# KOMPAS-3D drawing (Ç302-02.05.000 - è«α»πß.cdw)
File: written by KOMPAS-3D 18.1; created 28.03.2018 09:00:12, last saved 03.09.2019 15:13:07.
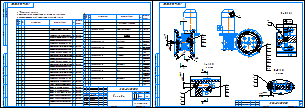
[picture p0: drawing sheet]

Sheets 1-2: A3, landscape

Document properties: Автор: Милов; Полное имя файла: \\192.168.87.28\Konstructor_doc\Мембранные насосы\Мембранный электропривод\А302-00.00.000 - ASTRA-302 (МЭ200)\Чертежи ПВХ\..\3Д ПВХ\А302-01.05.000 - Корпус.a3d; Масса: 33.4594; Форматы листов документа: 2xA3

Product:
- Part/product: (unnamed)
  - Component: Подшипник 80х40х18 6208-2RS1 SKF  | pos. 21  | Раздел спецификации: Стандартные изделия
  - Component: Шайба C.8.21 ГОСТ 11371-78  | pos. 20  | Раздел спецификации: Стандартные изделия; Примечание: Нерж.
  - Component: Шайба C.5.21 ГОСТ 11371-78  | pos. 19  | Раздел спецификации: Стандартные изделия; Примечание: Нерж.
  - Component: Шайба C 8 ГОСТ 6958-78  | pos. 18  | Раздел спецификации: Стандартные изделия; Примечание: Нерж.
  - Component: Шайба 8 ГОСТ 6402-70  | pos. 17  | Раздел спецификации: Стандартные изделия; Примечание: Нерж.
  - Component: Шайба 5 ГОСТ 6402-70  | pos. 16  | Раздел спецификации: Стандартные изделия; Примечание: Нерж.
  - Component: Кольцо A40.65Г ГОСТ 13942-86  | pos. 15  | Раздел спецификации: Стандартные изделия
  - Component: Гайка М8-6H ГОСТ 5915-70  | pos. 14  | Раздел спецификации: Стандартные изделия; Примечание: Нерж.
  - Component: Винт с цилиндрической головкой. / и шестигранным углублением под ключ / ГОСТ Р ИСО 4762-М8 x 45  | pos. 13  | Раздел спецификации: Стандартные изделия; Примечание: Нерж.
  - Component: Винт с цилиндрической головкой. / и шестигранным углублением под ключ / ГОСТ Р ИСО 4762-М8 x 35  | pos. 12  | Раздел спецификации: Стандартные изделия; Примечание: Нерж.
  - Component: Винт с цилиндрической головкой. / и шестигранным углублением под ключ / ГОСТ Р ИСО 4762-М5 x 16  | pos. 11  | Раздел спецификации: Стандартные изделия; Примечание: Нерж.
  - Component: Винт с цилиндрической головкой. / и шестигранным углублением под ключ / ГОСТ Р ИСО 4762-М5 x 12  | pos. 10  | Раздел спецификации: Стандартные изделия; Примечание: Нерж.
  - Component: Винт с потайной головкой / и шестигранным углублением под ключ / ГОСТ Р ИСО 10642-М4 x 20  | pos. 9  | Раздел спецификации: Стандартные изделия; Примечание: Нерж.
  - Component: Болт М8-6gx30 ГОСТ 7805-70  | pos. 8  | Раздел спецификации: Стандартные изделия; Примечание: Нерж.
  - Component: Фиксатор  | designation А302-01.05.015  | pos. 7  | Раздел спецификации: Детали; Форматы листов документа: А4; Примечание: Сталь 40  / ГОСТ 1050-2013 / @2~20
  - Component: Упор  | designation А302-01.05.014  | pos. 6  | Раздел спецификации: Детали; Форматы листов документа: А3; Примечание: Сталь 20  / ГОСТ 1050-2013 / Лист 30
  - Component: Фиксатор  | designation А302-01.05.012  | pos. 5  | Раздел спецификации: Детали; Форматы листов документа: А3; Примечание: Д16Т ГОСТ 4784-97 / Лист 20
  - Component: Ловитель  | designation А302-01.05.011  | pos. 4  | Раздел спецификации: Детали; Форматы листов документа: А4; Примечание: Сталь 40  / ГОСТ 1050-2013 / @2~10
  - Component: Ловитель  | designation А302-01.05.002  | pos. 3  | Раздел спецификации: Детали; Форматы листов документа: А3; Примечание: Фторопласт-4 / ГОСТ 10007-80 Е / @2~50
  - Component: Основание  | designation А302-01.05.001  | pos. 2  | Раздел спецификации: Детали; Форматы листов документа: А3; Примечание: Стержень ПВХ / @2~300
  - Component: Мотор-редуктор  | designation А302-02.20.000  | pos. 1  | Раздел спецификации: Сборочные единицы; Форматы листов документа: 2xA3; Примечание: *)2xA3

Title block, sheet 1: Наименование: Корпус; designation: А302-02.05.000; Масса: 33,46; scale: 1:4; sheet number: 1; Количество листов документа: 2; organisation: АО «Астерион»; Форматы листов документа: A3; stored path: Z:\Мембранные насосы\Мембранный электропривод\А302-00.00.000 - ASTRA-302 (МЭ200)\Чертежи\А302-00.05.000 - Корпус.cdw; Разработал: Лифлянд; Проверил: Борисенко; Т. контр.: Лучихин; Утвердил: Григорьева
Title block, sheet 2: sheet number: 2; stored path: Z:\Мембранные насосы\Мембранный электропривод\А302-00.00.000 - ASTRA-302 (МЭ200)\3Д ПВХ\А302-01.05.000 - Корпус.cdw

Views: Разрез А-А, Разрез Б-Б, Разрез В-В
Referenced files in D:\Мембранные насосы\Мембранный электропривод\А302-00.00.000 - ASTRA-302 (МЭ200)\3Д ПВХ\Отработка\: А302-01.20.000 - Мотор-редуктор.a3d, А302-01.05.002 - Ловитель.m3d, Упор-1.m3d, Фиксатор.m3d
Referenced files in Z:\Мембранные насосы\Мембранный электропривод\А302-00.00.000 - ASTRA-302 (МЭ200)\3Д ПВХ\: А302-01.20.000 - Мотор-редуктор.cdw
Referenced files in D:\Мембранные насосы\Мембранный электропривод\А302-00.00.000 - ASTRA-302 (МЭ200)\3Д ПВХ\: А302-01.05.002 - Ловитель.cdw, А302-01.05.001 - Основание.m3d, А302-01.05.001 - Основание.cdw, А302-01.05.012 - Фиксатор.m3d, А302-01.05.012 - Фиксатор.cdw, А302-01.05.014 - Упор.cdw, А302-01.05.011 - Ловитель.m3d, А302-01.05.011 - Ловитель.cdw, А302-01.05.015 - Фиксатор.m3d, А302-01.05.015 - Фиксатор.cdw, А302-01.20.001 - Основание.m3d, А302-01.35.000 - Фланец.a3d, А302-01.20.002 - Эксцентрик.m3d, А302-01.05.000 - Корпус.a3d
Referenced files in D:\1 ПКИ 3D\1 Крепеж стандартный\Подшипник\: Подшипник 80х40х18 6208-2RS1 SKF.m3d, Подшипник 52х25х15 62052RSH SKF.m3d
Referenced files in D:\1 ПКИ 3D\Двигатели\АИР\: Электродвигатель АИР 80А4 IM 3081 1,1кВт 1400 об..m3d
Referenced files in D:\1 ПКИ 3D\Редуктора NMRW\Редукторы\: Редуктор NMRW 063.m3d, Червячный мотор-редуктор NMRV063 АИР80.a3d
Referenced files in D:\Мембранные насосы\Мембранный электропривод\А302-00.00.000 - ASTRA-302 (МЭ200)\3Д\: А302-00.35.002 - Пластина.m3d, А302-00.35.001 - Труба 140х140х4.m3d, А302-00.20.004 - Вал.m3d, А302-00.20.003 - Ползун.m3d, А302-00.05.001 - Основание.m3d
Referenced files in C:\Program Files\ASCON\KOMPAS-3D v18\Libs\PartLib\DATA\VAULT\methods\kompas\3d\: PLib_Check_spring_rings_GOST_13942_911.m3d, PLib_Washer_1_712.m3d, PLib_Bolt_1_900.m3d, PLib_Washer_2_712.m3d, PLib_Nut_OST92_900.m3d, PLib_Screw_DIN_7984_1500.m3d, PLib_Key_prismatic_712.m3d, PLib_Screw_ISO_10642_1500.m3d
Referenced files in C:\Program Files\ASCON\KOMPAS-3D V16\Libs\PartLib\DATA\VAULT\Methods\kompas\3d\: PLib_Bolt_1_900.m3d
Referenced files in Z:\Мембранные насосы\Мембранный электропривод\А302-00.00.000 - ASTRA-302 (МЭ200)\3Д\: А302-00.20.002 - Эксцентрик.m3d
Referenced files in \\192.168.87.28\Konstructor_doc\Мембранные насосы\Мембранный электропривод\А302-00.00.000 - ASTRA-302 (МЭ200)\3Д ПВХ\Отработка\: А302-01.05.000 - Корпус.a3d, Фиксатор.m3d, Упор-1.m3d
Referenced files in C:\Program Files\ASCON\KOMPAS-3D V16\Libs\PartLib\DATA\vault\Methods\Kompas\3D\: PLib_Check_spring_rings_GOST_13942_911.m3d, PLib_Washer_2_712.m3d, PLib_Washer_1_712.m3d, PLib_Screw_DIN_7984_1500.m3d
Referenced files in \\192.168.87.28\Konstructor_doc\Мембранные насосы\Мембранный электропривод\А302-00.00.000 - ASTRA-302 (МЭ200)\3Д\: А302-00.20.004 - Вал.m3d, А302-00.35.001 - Труба 140х140х4.m3d, А302-00.35.002 - Пластина.m3d, А302-00.20.003 - Ползун.m3d
Referenced files in \\192.168.87.28\Konstructor_doc\1 ПКИ 3D\Двигатели\АИР\: Электродвигатель АИР 80А4 IM 3081 1,1кВт 1400 об..m3d
Referenced files in \\192.168.87.28\Konstructor_doc\Мембранные насосы\Мембранный электропривод\А302-00.00.000 - ASTRA-302 (МЭ200)\3Д ПВХ\: А302-01.20.002 - Эксцентрик.m3d, А302-01.05.001 - Основание.m3d, А302-01.05.011 - Ловитель.m3d, А302-01.05.012 - Фиксатор.m3d, А302-01.05.015 - Фиксатор.m3d
Referenced files in \\192.168.87.28\Konstructor_doc\1 ПКИ 3D\1 Крепеж стандартный\Подшипник\: Подшипник 80х40х18 6208-2RS1 SKF.m3d, Подшипник 52х25х15 62052RSH SKF.m3d
Referenced files in \\192.168.87.28\Konstructor_doc\1 ПКИ 3D\Редуктора NMRW\Редукторы\: Редуктор NMRW 063.m3d
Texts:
  Мотор-редуктор
  @100~)2xA3
  Ловитель
  Основание
  Шайба C.8.21 ГОСТ 11371-78
  Крепежное изделие ГОСТ
  Шайба
  ГОСТ
  нерж.
  Сталь 12Х18Н10Т ГОСТ 5632-72
  Шайба C 8 ГОСТ 6958-78
  Сталь 20 ГОСТ 1050-2013
  Шайба C 8.04.019 ГОСТ 6958-78
  Шайба 8 ГОСТ 6402-70
  Сталь 30Х13 ГОСТ 5632-72
  Шайба 8 30Х13 019 ГОСТ 6402-70
  Болт М8-6gx30 ГОСТ 7805-70
  Болт
  Болт М8-6gx30.58.019 ГОСТ 7805-70
  Гайка М8-6H ГОСТ 5915-70
  Гайка
  Гайка М8-6H.5.019 ГОСТ 5915-70
  Подшипник 80х40х18 6208-2RS1 SKF
  Подшипник
  SKF
  Фиксатор
  Упор
  Шайба C.5.21 ГОСТ 11371-78
  Шайба 5 ГОСТ 6402-70
  Винт с цилиндрической головкой
  и шестигранным углублением под ключ
  ГОСТ Р ИСО  4762-М5 x 16
  Винт с цилиндрической головкой и шестигранным углублением под ключ
  Р ИСО
  Сталь
  Шайба 5 30Х13 019 ГОСТ 6402-70
  Винт с цилиндрической головкой и шестигранным углублением под ключ ГОСТ Р ИСО  4762-М5 x 16-6.8-A9J
  ГОСТ Р ИСО  4762-М5 x 12
  Винт с цилиндрической головкой и шестигранным углублением под ключ ГОСТ Р ИСО  4762-М5 x 12-6.8-A9J
  Винт с потайной головкой
  ГОСТ Р ИСО  10642-М4 x 20
  Винт с потайной головкой и шестигранным углублением под ключ
  Винт с потайной головкой и шестигранным углублением под ключ ГОСТ Р ИСО  10642-М4 x 20-8.8-A3J
  ГОСТ Р ИСО  4762-М8 x 45
  Винт с цилиндрической головкой и шестигранным углублением под ключ ГОСТ Р ИСО  4762-М8 x 45-6.8-A9J
  ГОСТ Р ИСО  4762-М8 x 35
  Винт с цилиндрической головкой и шестигранным углублением под ключ ГОСТ Р ИСО  4762-М8 x 35-6.8-A9J
  Кольцо A40.65Г ГОСТ 13942-86
  Кольцо
  Сталь 65Г ГОСТ 14959-79
  Винт
  потайной
  головкой
  шестигранным
  углублением
  под
  ключ
  ИСО
  цилиндрической
  *)2xA3
  Стержень ПВХ
  Стержень ПВХ / @2~300
  Фторопласт-4
  ГОСТ 10007-80 Е
  Фторопласт-4 / ГОСТ 10007-80 Е / @2~50
  Сталь 40
  ГОСТ 1050-2013
  Сталь 40  / ГОСТ 1050-2013 / @2~10
  Д16Т ГОСТ 4784-97
  Лист 20
  Д16Т ГОСТ 4784-97 / Лист 20
  Сталь 20
  Лист 30
  Сталь 20  / ГОСТ 1050-2013 / Лист 30
  Сталь 40  / ГОСТ 1050-2013 / @2~20
  Нерж.
  ГОСТ Р ИСО 10642-М4 x 20
  Винт с цилиндрической головкой.
  ГОСТ Р ИСО 4762-М5 x 12
  ГОСТ Р ИСО 4762-М5 x 16
  ГОСТ Р ИСО 4762-М8 x 35
  ГОСТ Р ИСО 4762-М8 x 45
  Электродвигатель / АИР 80А4 IM 3081 1,1кВт 1400 об/мин
  Редуктор NMRW 063
  Мотор-редуктор / NMRV063 N P(кВт) V5 / P(мощн./дв.), i(передат. отн.) см. заказ
  Пластина
  Труба 140х140х4
  Фланец
  Эксцентрик
  Кольцо A25.65Г ГОСТ 13942-86
  Подшипник 52х25х15 62052RSH SKF
  Вал
  Ползун
  Шайба C.5.04.019 ГОСТ 11371-78
  Болт М5-6gx35.58.019 ГОСТ 7805-70
  Гайка М5-6H.5.019 ГОСТ 5915-70
  Винт с цилиндрической головкой и шестигранным углублением под ключ ГОСТ Р ИСО 4762 - М8 x 25 - A2-70
  Винт с цилиндрической головкой и шестигранным углублением под ключ ГОСТ Р ИСО 4762 - М8 x 35 - A2-70
  Гайка М8-6H.21.12Х18Н10Т ГОСТ 5915-70
  Шпонка 8x7x90 ГОСТ 23360-78
Dimensions and other numbers on the sheet: 4; 1; 3; 2; 20; 21; 40Х; 019; 18; 8; 04; 17; 58; 30Х13; 14; 5; 6; 19; 16; 11; 6.8; 10; 9; 8.8; 13; 12; 15; 65Г; 7; 34; 0; 46; 42; 54; 49; 44; 30; 31; 40; 51; 53; 41; 22; 1:4; 33,46

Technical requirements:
  *Размеры для справок.
  Фиксатор поз.5 установить по месту см. разрез В-В.
  Винт потай М4 поз.9 стопорить краской в резьбу.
